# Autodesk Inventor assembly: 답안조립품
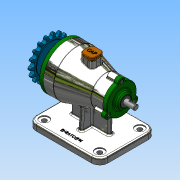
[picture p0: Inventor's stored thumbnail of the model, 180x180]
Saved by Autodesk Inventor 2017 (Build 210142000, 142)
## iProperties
Part Number: 답안조립품
Material: 일반
Document SubType Name: Assembly
Designer: user
Author: user
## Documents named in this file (16)
- C:\Users\user\Desktop\711006V1014\답안조립품.iam
- C:\Users\user\Desktop\711006V1014\본체.ipt
- C:\Users\user\Desktop\711006V1014\앞커버.ipt
- C:\Users\user\Desktop\711006V1014\뒤커버.ipt
- C:\Users\user\Desktop\711006V1014\오일 실 10x20x7.ipt
- C:\Users\user\Desktop\711006V1014\오일 실 17x30x8.ipt
- C:\Users\user\Desktop\711006V1014\베어링 6203.ipt
- C:\Users\user\Desktop\711006V1014\베어링 6200.ipt
- C:\Users\user\Desktop\711006V1014\축.ipt
- C:\Users\user\Desktop\711006V1014\키 5x5.ipt
- 키 5 x 5.ipt
- C:\Users\user\Desktop\711006V1014\스프로킷.ipt
- C:\Users\user\Desktop\711006V1014\마개.ipt
- C:\Users\user\Desktop\711006V1014\와셔.ipt
- C:\Users\user\Desktop\711006V1014\볼트 M4.ipt
- 볼트 M4 x 12.ipt
